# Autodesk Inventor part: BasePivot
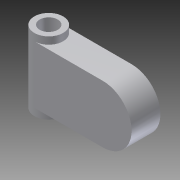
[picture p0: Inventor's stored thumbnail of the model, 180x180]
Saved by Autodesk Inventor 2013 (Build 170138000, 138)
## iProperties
Created: 2004-11
Document SubType Name: Modeling
Designer: Autodesk, Inc.
Manufacturer: Standard
Standards Organization: Custom
Description: SWING ARM, BASE PIVOT
Mass: 110.316 g
Surface Area: 195.652 cm^2
Volume: 110.316 cm^3
Density: 1 g/cm^3
Material: Allgemein
CAGE: 1LJX3
Dept. ID: Product Design
Description #2: ---
Finish #1: ---
Finish #2: ---
Material ID: ---
Project Number: ---
Author: Autodesk, Inc.
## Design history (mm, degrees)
revolve "Revolution1" stored, may be unused: angle "d2" = 90 deg
sketch "Sketch2"
  geometry: L1 (0, -35.56)-(0, 35.56) reference; L2 (0, 25.4)-(60.325, 25.4); L3 (60.325, 25.4)-(60.325, -25.4); L4 (60.325, -25.4)-(0, -25.4); L5 (0, -25.4)-(0, 25.4); 3 further points
  constraints: 8 end point, 2 parallel, 1 coincident, 1 horizontal, 1 horizontal alignment, 1 midpoint, 1 perpendicular, 1 point on line, 1 vertical alignment, 2 other
  dimensions: "d3" = 60.325 distance of L2.start L2.end; "d4" = 50.8 distance of L2.end L3.end
extrude "Extrusion1" join sketch "Sketch2" stored distance "d5" = 25.4; taper "d6" = 0 deg
sketch "Sketch3"
  geometry: C1 r 12.7 at (0, 0) reference; C2 r 7.938 at (0, 0)
  constraints: 1 centre point
  dimensions: "d7" = 15.875 diameter of C2
extrude "Extrusion2" cut sketch "Sketch3" stored distance "d8" = 25.4; taper "d9" = 0 deg
body "Solid1"
sketch "Sketch1"
  geometry: L1 (0, 31.75)-(12.7, 31.75); L2 (12.7, 31.75)-(12.7, -31.75); L3 (12.7, -31.75)-(0, -31.75); L4 (0, -31.75)-(0, 31.75); 2 further points
  constraints: 8 end point, 2 midpoint, 2 parallel, 1 coincident, 1 horizontal, 1 perpendicular, 1 other
  dimensions: "d0" = 25.4 diameter of L2 L4; "d1" = 63.5 distance of L1.end L2.end
